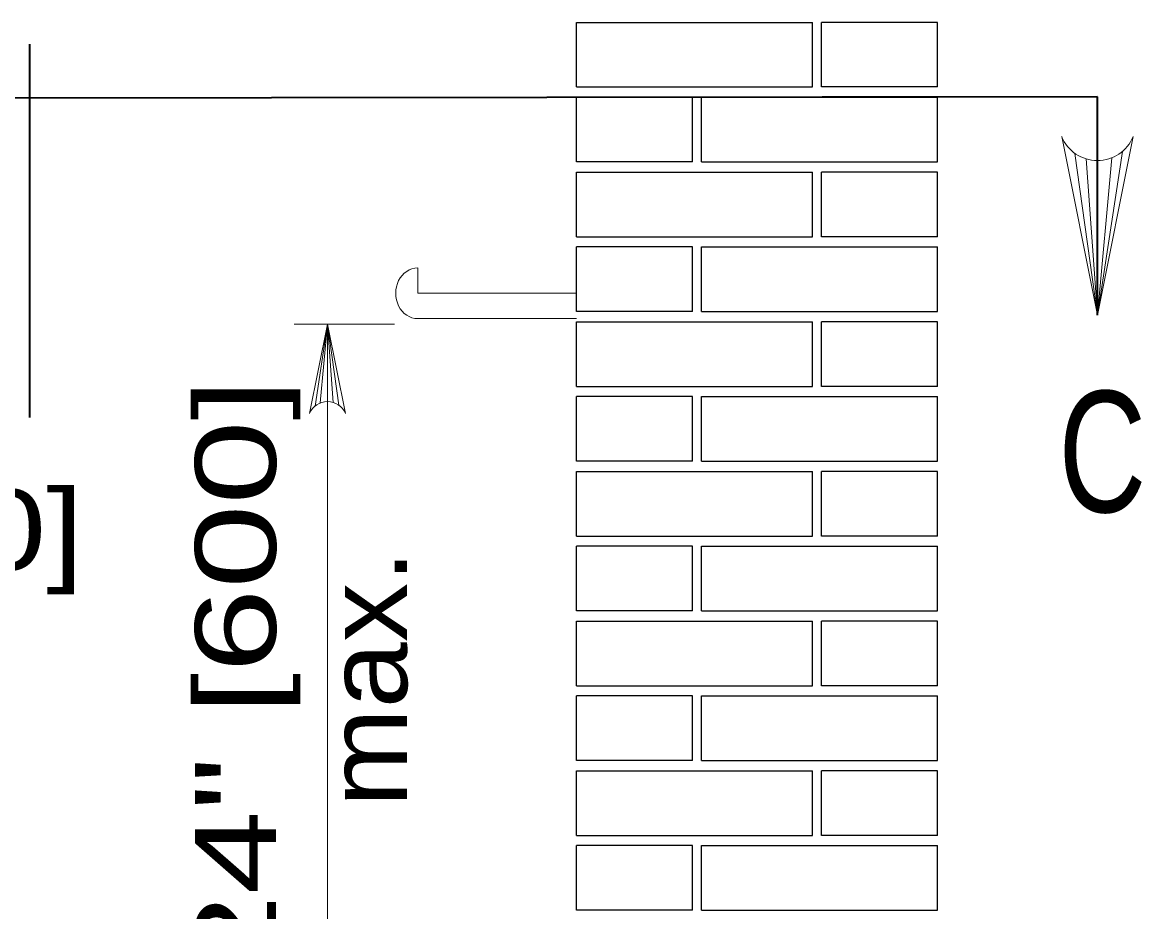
# Model space of a CAD drawing. Extents: x 750.7 to 784.7, y 860.1 to 882.1.
# Drawn here: x 763.779 to 765.996, y 864.82 to 866.581 of the extents above; entities that cross this region are included whole.
import ezdxf
from ezdxf.enums import TextEntityAlignment as Align

# ---------------------------------------------------------------- set-up
doc = ezdxf.new("R2010")
doc.units = 0
doc.header["$LTSCALE"] = 0.064
doc.layers.add('1', color=7, linetype='Continuous', lineweight=13)

msp = doc.modelspace()

# ---------------------------------------------------------------- linework, layer by layer
at = {"layer": '1', "lineweight": 25}
for p, q in [((765.36175, 866.45333), (765.36175, 866.58133)), ((765.59183, 866.45333), (765.36175, 866.45333)), ((764.8765, 866.30508), (764.8765, 866.43308)), ((765.10658, 866.30508), (764.8765, 866.30508)), ((765.36175, 866.15675), (765.36175, 866.28483)), ((765.59183, 866.15675), (765.36175, 866.15675)), ((764.8765, 866.0085), (764.8765, 866.13658)), ((765.10658, 866.0085), (764.8765, 866.0085)), ((765.36175, 865.86025), (765.36175, 865.98833)), ((765.59183, 865.86025), (765.36175, 865.86025)), ((764.8765, 865.712), (764.8765, 865.84)), ((765.10658, 865.712), (764.8765, 865.712)), ((765.36175, 865.56375), (765.36175, 865.69175)), ((765.59183, 865.56375), (765.36175, 865.56375)), ((764.8765, 865.41542), (764.8765, 865.5435)), ((765.10658, 865.41542), (764.8765, 865.41542)), ((765.36175, 865.26717), (765.36175, 865.39525)), ((765.59183, 865.26717), (765.36175, 865.26717)), ((764.8765, 865.11892), (764.8765, 865.247)), ((765.10658, 865.11892), (764.8765, 865.11892)), ((765.36175, 864.97067), (765.36175, 865.09875)), ((765.59183, 864.97067), (765.36175, 864.97067)), ((764.8765, 864.82242), (764.8765, 864.95042)), ((765.10658, 864.82242), (764.8765, 864.82242))]:
    msp.add_line(p, q, dxfattribs=at)
at = {"layer": '1', "lineweight": 35}
for p, q in [((763.79367, 865.79842), (763.79367, 866.53833)), ((765.90858, 866.43392), (760.30408, 866.42633)), ((765.90858, 866.00108), (765.90858, 866.43392))]:
    msp.add_line(p, q, dxfattribs=at)
at = {"layer": '1'}
for p, q in [((765.86367, 866.32175), (765.90858, 866.00108)), ((765.95817, 866.3255), (765.90858, 866.00108)), ((765.88592, 866.31083), (765.90858, 866.00108)), ((765.93733, 866.31325), (765.90858, 866.00108)), ((765.90858, 866.30758), (765.90858, 866.00108)), ((764.56192, 866.04467), (764.56192, 866.09475)), ((764.56192, 866.04467), (764.87642, 866.04467)), ((764.51583, 865.98342), (764.31717, 865.98342)), ((764.3585, 865.82117), (764.38325, 865.98342)), ((764.36883, 865.82733), (764.38325, 865.98342)), ((764.38325, 864.89192), (764.38325, 865.98342)), ((764.38325, 865.83017), (764.38325, 865.98342)), ((764.39458, 865.8285), (764.38325, 865.98342)), ((764.40567, 865.82308), (764.38325, 865.98342)), ((764.56192, 865.99458), (764.87642, 865.99458)), ((764.38325, 864.48525), (764.38325, 864.95308))]:
    msp.add_line(p, q, dxfattribs=at)
at = {"layer": '1', "lineweight": 25}
for points in [[(764.8765, 866.45333), (764.8765, 866.58133), (765.34417, 866.58133)], [(764.8765, 866.45333), (765.34417, 866.45333), (765.34417, 866.58133)], [(765.59183, 866.45333), (765.59183, 866.58133), (765.36175, 866.58133)], [(765.10658, 866.30508), (765.10658, 866.43308), (764.8765, 866.43308)], [(765.12425, 866.30508), (765.12425, 866.43308), (765.59192, 866.43308)], [(765.12425, 866.30508), (765.59192, 866.30508), (765.59192, 866.43308)], [(764.8765, 866.15675), (764.8765, 866.28483), (765.34417, 866.28483)], [(764.8765, 866.15675), (765.34417, 866.15675), (765.34417, 866.28483)], [(765.59183, 866.15675), (765.59183, 866.28483), (765.36175, 866.28483)], [(765.10658, 866.0085), (765.10658, 866.13658), (764.8765, 866.13658)], [(765.12425, 866.0085), (765.12425, 866.13658), (765.59192, 866.13658)], [(765.12425, 866.0085), (765.59192, 866.0085), (765.59192, 866.13658)], [(764.8765, 865.86025), (764.8765, 865.98833), (765.34417, 865.98833)], [(764.8765, 865.86025), (765.34417, 865.86025), (765.34417, 865.98833)], [(765.59183, 865.86025), (765.59183, 865.98833), (765.36175, 865.98833)], [(765.10658, 865.712), (765.10658, 865.84), (764.8765, 865.84)], [(765.12425, 865.712), (765.12425, 865.84008), (765.59192, 865.84008)], [(765.12425, 865.712), (765.59192, 865.712), (765.59192, 865.84008)], [(764.8765, 865.56375), (764.8765, 865.69175), (765.34417, 865.69175)], [(764.8765, 865.56375), (765.34417, 865.56375), (765.34417, 865.69175)], [(765.59183, 865.56375), (765.59183, 865.69175), (765.36175, 865.69175)], [(765.10658, 865.41542), (765.10658, 865.5435), (764.8765, 865.5435)], [(765.12425, 865.4155), (765.12425, 865.5435), (765.59192, 865.5435)], [(765.12425, 865.4155), (765.59192, 865.4155), (765.59192, 865.5435)], [(764.8765, 865.26717), (764.8765, 865.39525), (765.34417, 865.39525)], [(764.8765, 865.26717), (765.34417, 865.26717), (765.34417, 865.39525)], [(765.59183, 865.26717), (765.59183, 865.39525), (765.36175, 865.39525)], [(765.10658, 865.11892), (765.10658, 865.247), (764.8765, 865.247)], [(765.12425, 865.11892), (765.12425, 865.247), (765.59192, 865.247)], [(765.12425, 865.11892), (765.59192, 865.11892), (765.59192, 865.247)], [(764.8765, 864.97067), (764.8765, 865.09875), (765.34417, 865.09875)], [(764.8765, 864.97067), (765.34417, 864.97067), (765.34417, 865.09875)], [(765.59183, 864.97067), (765.59183, 865.09875), (765.36175, 865.09875)], [(765.10658, 864.82242), (765.10658, 864.95042), (764.8765, 864.95042)], [(765.12425, 864.82242), (765.12425, 864.9505), (765.59192, 864.9505)], [(765.12425, 864.82242), (765.59192, 864.82242), (765.59192, 864.9505)]]:
    msp.add_lwpolyline(points, dxfattribs=at)
at = {"layer": '1'}
for points in [[(765.97942, 866.35525), (765.90858, 866.00108), (765.83775, 866.35525)], [(764.34783, 865.80633), (764.38325, 865.98342), (764.41867, 865.80633)]]:
    msp.add_lwpolyline(points, dxfattribs=at)
for centre, radius, start, end in [((765.90849, 866.38387), 0.07644, 202.08782, 337.91395), ((764.3833, 865.79201), 0.03822, 22.08782, 157.91395)]:
    msp.add_arc(centre, radius, start, end, dxfattribs=at)
msp.add_ellipse((764.56192, 866.04466), major_axis=(0, 0.05012), ratio=0.869565, start_param=0.000003, end_param=3.1415958, dxfattribs=at)

# ---------------------------------------------------------------- texts
for s, width, p in [('24" [600]', 1.4, (764.281, 865.28138)), ('max.', 1.1, (764.541, 865.28142))]:
    msp.add_text(s, height=0.16, rotation=90, dxfattribs=dict(at, width=width)).set_placement(p, align=Align.CENTER)
at = {"layer": '1', "width": 0.75}
msp.add_text('C', height=0.24, dxfattribs=at).set_placement((765.83142, 865.611))
at = {"layer": '1', "width": 1.25}
msp.add_text('6"[150]', height=0.16, dxfattribs=at).set_placement((763.481, 865.49642), align=Align.CENTER)

doc.saveas('drawing.dxf')
